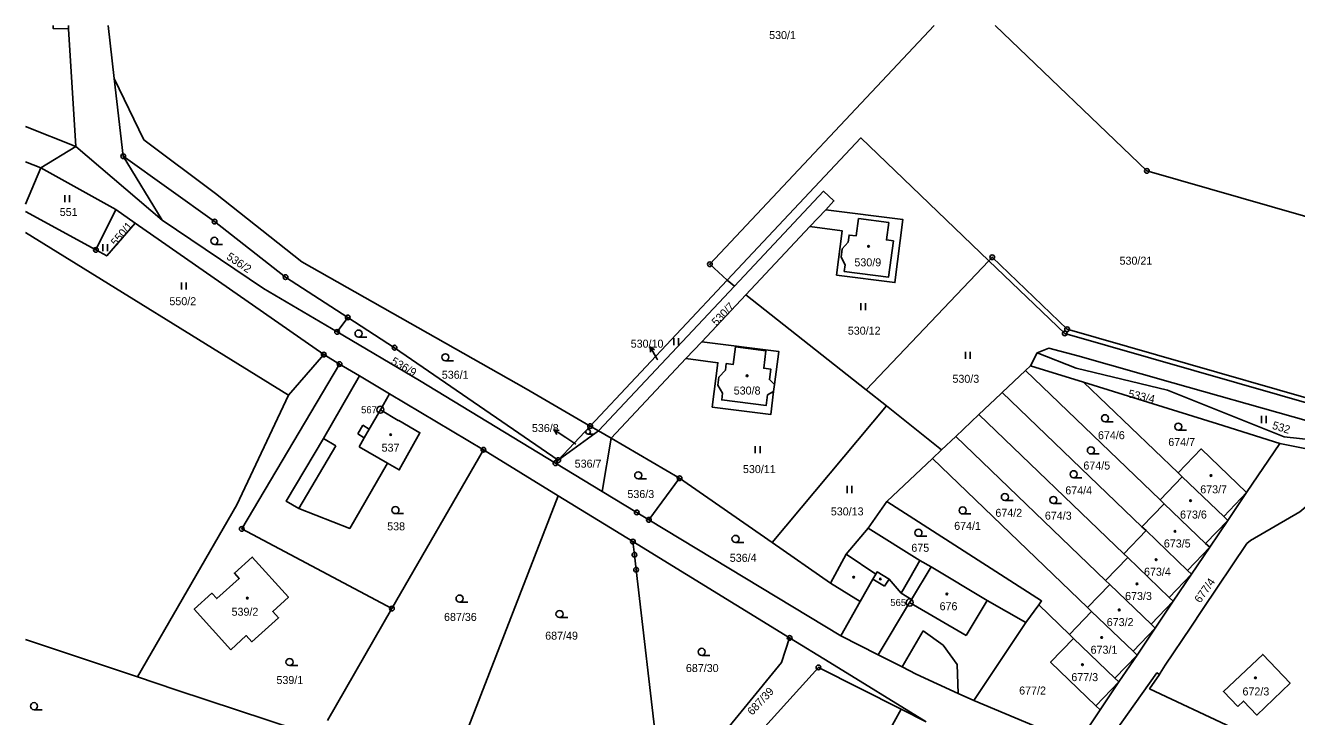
# Model space of a CAD drawing. Extents: x -749778 to -749372, y -967291 to -966955.
# Drawn here: x -749777.6 to -749507.7, y -967101.9 to -966955.1 of the extents above; entities that cross this region are included whole.
import ezdxf

# ---------------------------------------------------------------- set-up
doc = ezdxf.new("R2010")
doc.units = 0
for name, color, linetype in [('Hranice parcel', 7, 'Continuous'), ('Parcelní čísla', 7, 'Continuous'), ('Pop  PČ popisy', 7, 'Continuous'), ('Vnitřní kresba', 7, 'Continuous'), ('Značky bodu BP', 7, 'Continuous'), ('Značky budov', 7, 'Continuous'), ('Značky kultur', 7, 'Continuous')]:
    doc.layers.add(name, color=color, linetype=linetype)

msp = doc.modelspace()

# ---------------------------------------------------------------- linework, layer by layer
at = {"layer": 'Hranice parcel'}
for p, q in [((-749768.49, -966955.06), (-749768.51, -966955.82)), ((-749768.51, -966955.82), (-749766.93, -966980.78)), ((-749756.87, -966982.87), (-749758.78, -966966.32)), ((-749766.93, -966980.78), (-749777.63, -966976.54)), ((-749774.34, -966985.3), (-749766.93, -966980.78)), ((-749766.93, -966980.78), (-749748.6, -966996.42)), ((-749748.6, -966996.42), (-749756.87, -966982.87)), ((-749774.34, -966985.3), (-749777.63, -966984.05)), ((-749758.43, -966994.19), (-749774.34, -966985.3)), ((-749758.43, -966994.19), (-749762.66, -967002.76)), ((-749754.33, -966997.05), (-749758.43, -966994.19)), ((-749611.05, -966997.82), (-749607.66, -966994.22)), ((-749714.28, -967025), (-749754.33, -966997.05)), ((-749721.74, -967033.62), (-749777.63, -966999.06)), ((-749624.66, -967012.31), (-749611.05, -966997.82)), ((-749573, -967005.05), (-749599.06, -967032.48)), ((-749657.69, -967040.19), (-749628.61, -967009.22)), ((-749627.02, -967010.45), (-749655.92, -967041.22)), ((-749627.02, -967010.45), (-749628.61, -967009.22)), ((-749634, -967022.26), (-749624.66, -967012.31)), ((-749599.06, -967032.48), (-749624.66, -967012.31)), ((-749711.43, -967020.19), (-749709.16, -967017.1)), ((-749637.38, -967025.86), (-749634, -967022.26)), ((-749721.74, -967033.62), (-749714.28, -967025)), ((-749714.28, -967025), (-749710.9, -967027.02)), ((-749706.67, -967029.54), (-749710.9, -967027.02)), ((-749653.26, -967042.77), (-749637.38, -967025.86)), ((-749564.16, -967027.37), (-749562.74, -967024.63)), ((-749700.29, -967033.34), (-749706.67, -967029.54)), ((-749570.18, -967033.07), (-749565.25, -967028.4)), ((-749565.25, -967028.4), (-749564.16, -967027.37)), ((-749536.64, -967055.87), (-749565.25, -967028.4)), ((-749564.16, -967027.37), (-749552.89, -967030.87)), ((-749532.8, -967050.13), (-749552.89, -967030.87)), ((-749680.37, -967045.22), (-749700.29, -967033.34)), ((-749599.06, -967032.48), (-749594.75, -967035.91)), ((-749540.5, -967061.59), (-749570.18, -967033.07)), ((-749619.07, -967064.92), (-749594.75, -967035.91)), ((-749594.75, -967035.91), (-749583.06, -967045.24)), ((-749580.06, -967042.41), (-749575.13, -967037.74)), ((-749544.33, -967067.31), (-749575.13, -967037.74)), ((-749664.47, -967047.42), (-749657.69, -967040.19)), ((-749655.92, -967041.22), (-749657.69, -967040.19)), ((-749655.92, -967041.22), (-749664.47, -967047.42)), ((-749655.92, -967041.22), (-749653.26, -967042.77)), ((-749653.26, -967042.77), (-749655.12, -967054.12)), ((-749638.69, -967051.26), (-749653.26, -967042.77)), ((-749583.06, -967045.24), (-749580.06, -967042.41)), ((-749548.22, -967073.01), (-749580.06, -967042.41)), ((-749699.81, -967078.98), (-749680.37, -967045.22)), ((-749680.37, -967045.22), (-749664.5, -967054.98)), ((-749583.06, -967045.24), (-749585.01, -967047.08)), ((-749518.29, -967054.31), (-749511.23, -967043.86)), ((-749664.47, -967047.42), (-749665.08, -967048.07)), ((-749655.12, -967054.12), (-749665.08, -967048.07)), ((-749585.01, -967047.08), (-749594.68, -967056.22)), ((-749552.05, -967078.75), (-749585.01, -967047.08)), ((-749645.2, -967060.11), (-749638.69, -967051.26)), ((-749619.07, -967064.92), (-749638.69, -967051.26)), ((-749531.93, -967050.96), (-749536.64, -967055.87)), ((-749532.8, -967050.13), (-749531.93, -967050.96)), ((-749684.12, -967105.59), (-749664.5, -967054.98)), ((-749664.5, -967054.98), (-749648.62, -967064.74)), ((-749535.77, -967056.7), (-749540.5, -967061.59)), ((-749536.64, -967055.87), (-749535.77, -967056.7)), ((-749522.26, -967060.23), (-749518.29, -967054.31)), ((-749604.44, -967084.74), (-749645.2, -967060.11)), ((-749540.5, -967061.59), (-749539.64, -967062.41)), ((-749526.12, -967065.95), (-749522.26, -967060.23)), ((-749648.62, -967064.74), (-749615.32, -967085.21)), ((-749539.64, -967062.41), (-749544.33, -967067.31)), ((-749606.68, -967073.54), (-749619.07, -967064.92)), ((-749603.32, -967067.37), (-749606.68, -967073.54)), ((-749544.33, -967067.31), (-749543.47, -967068.14)), ((-749529.98, -967071.67), (-749526.12, -967065.95)), ((-749543.47, -967068.14), (-749548.22, -967073.01)), ((-749533.84, -967077.4), (-749529.98, -967071.67)), ((-749547.35, -967073.84), (-749552.05, -967078.75)), ((-749548.22, -967073.01), (-749547.35, -967073.84)), ((-749565.15, -967081.89), (-749562.42, -967078.16)), ((-749562.42, -967078.16), (-749555.87, -967084.45)), ((-749537.69, -967083.12), (-749533.84, -967077.4)), ((-749699.81, -967078.98), (-749713.49, -967102.74)), ((-749551.19, -967079.58), (-749555.87, -967084.45)), ((-749552.05, -967078.75), (-749551.19, -967079.58)), ((-749576.24, -967098.5), (-749565.15, -967081.89)), ((-749541.54, -967088.85), (-749537.69, -967083.12)), ((-749555.87, -967084.45), (-749555.02, -967085.29)), ((-749545.4, -967094.56), (-749541.54, -967088.85)), ((-749549.38, -967100.48), (-749545.4, -967094.56)), ((-749576.24, -967098.5), (-749554.23, -967107.67)), ((-749586.36, -967103.02), (-749591.67, -967100.33))]:
    msp.add_line(p, q, dxfattribs=at)
for points in [[(-749768.51, -966955.82), (-749771.73, -966955.75), (-749771.71, -966955.06)], [(-749758.78, -966966.32), (-749760.08, -966955.06)], [(-749628.61, -967009.22), (-749632.26, -967005.8), (-749584.62, -966955.06)], [(-749571.65, -966955.06), (-749539.45, -966985.97), (-749459.63, -967008.89), (-749477.4, -967037.32)], [(-749758.78, -966966.32), (-749752.45, -966979.37), (-749737.29, -966990.76), (-749718.94, -967005.3), (-749671.29, -967032.27), (-749657.69, -967040.19)], [(-749573, -967005.05), (-749600.19, -966978.95), (-749628.61, -967009.22)], [(-749756.87, -966982.87), (-749737.45, -966996.74), (-749722.38, -967008.55), (-749709.16, -967017.1)], [(-749777.63, -966993.01), (-749774.34, -966985.3)], [(-749607.66, -966994.22), (-749605.92, -966992.36), (-749608.11, -966990.31), (-749627.02, -967010.45)], [(-749762.66, -967002.76), (-749777.63, -966994.6)], [(-749611.05, -966997.82), (-749604.17, -966998.69), (-749605.37, -967008.12), (-749592.97, -967009.7), (-749591.26, -966996.3), (-749607.66, -966994.22)], [(-749762.66, -967002.76), (-749760.36, -967004.02), (-749754.33, -966997.05)], [(-749711.43, -967020.19), (-749727.04, -967010.95), (-749748.6, -966996.42)], [(-749573, -967005.05), (-749572.31, -967004.33), (-749556.39, -967019.6), (-749480.03, -967041.53), (-749477.4, -967037.32)], [(-749474.68, -967044.11), (-749556.9, -967020.49), (-749573, -967005.05)], [(-749709.16, -967017.1), (-749699.22, -967023.53), (-749664.47, -967047.42)], [(-749665.08, -967048.07), (-749693.94, -967030.54), (-749711.43, -967020.19)], [(-749637.38, -967025.86), (-749630.55, -967026.73), (-749631.75, -967036.16), (-749619.35, -967037.74), (-749618.72, -967032.84), (-749618.54, -967031.36), (-749617.64, -967024.34), (-749634, -967022.26)], [(-749562.74, -967024.63), (-749560.29, -967023.62), (-749554.11, -967025.29), (-749533.97, -967031.01), (-749482.86, -967045.42)], [(-749710.9, -967027.02), (-749731.68, -967062.04), (-749699.81, -967078.98)], [(-749562.74, -967024.63), (-749554.44, -967027.88), (-749535.11, -967032.59), (-749510.28, -967042.45), (-749482.86, -967045.42)], [(-749706.67, -967029.54), (-749714.33, -967042.83), (-749722.22, -967056.16), (-749719.59, -967057.72), (-749708.76, -967061.94), (-749700.71, -967048.1), (-749698.23, -967049.52), (-749693.83, -967041.62), (-749698.3, -967038.99), (-749698.47, -967039.04), (-749702.24, -967036.72), (-749700.29, -967033.34)], [(-749552.89, -967030.87), (-749524.47, -967039.74), (-749511.23, -967043.86)], [(-749753.84, -967093.49), (-749732.73, -967056.95), (-749721.74, -967033.62)], [(-749575.13, -967037.74), (-749570.49, -967033.35), (-749570.18, -967033.07)], [(-749518.29, -967054.31), (-749527.96, -967045.04), (-749532.8, -967050.13)], [(-749511.23, -967043.86), (-749503.78, -967045.37), (-749490.3, -967048.1), (-749484.05, -967051.31)], [(-749522.26, -967060.23), (-749523.13, -967059.41), (-749531.93, -967050.96)], [(-749456.84, -967065.27), (-749475.82, -967057.43), (-749489.74, -967052.51), (-749500.28, -967053.21), (-749501.83, -967053.4), (-749502.46, -967054.34), (-749503.87, -967055.82), (-749506.95, -967058.39), (-749517.45, -967064.49), (-749518.23, -967065.16), (-749527.61, -967079.16), (-749530.11, -967082.89), (-749535.6, -967090.98), (-749536.66, -967092.72), (-749536.81, -967092.95)], [(-749645.2, -967060.11), (-749647.8, -967058.54), (-749655.12, -967054.12)], [(-749594.68, -967056.22), (-749598.63, -967061.85), (-749603.32, -967067.37)], [(-749594.68, -967056.22), (-749561.83, -967077.35), (-749562.42, -967078.16)], [(-749526.12, -967065.95), (-749526.97, -967065.13), (-749535.77, -967056.7)], [(-749648.62, -967064.74), (-749648.3, -967067.53), (-749647.94, -967070.71), (-749643.43, -967109.15)], [(-749529.98, -967071.67), (-749530.84, -967070.85), (-749539.64, -967062.41)], [(-749603.32, -967067.37), (-749597.01, -967071.63), (-749596.76, -967071.19), (-749594.16, -967072.69), (-749591.62, -967075.7), (-749589.79, -967072.47), (-749587.69, -967068.76), (-749585.3, -967070.11), (-749573.36, -967077.28), (-749565.15, -967081.89)], [(-749734.04, -967087.7), (-749741.77, -967079.12), (-749738.02, -967075.7), (-749737, -967076.84), (-749732.23, -967072.54), (-749733.26, -967071.41), (-749729.47, -967068.01), (-749721.76, -967076.51), (-749725.09, -967079.58), (-749723.88, -967080.9), (-749729.51, -967086), (-749730.74, -967084.72), (-749734.04, -967087.7)], [(-749533.84, -967077.4), (-749534.69, -967076.58), (-749543.47, -967068.14)], [(-749606.68, -967073.54), (-749600.38, -967077.49), (-749604.44, -967084.74)], [(-749537.69, -967083.12), (-749538.56, -967082.3), (-749547.35, -967073.84)], [(-749541.54, -967088.85), (-749542.39, -967088.02), (-749551.19, -967079.58)], [(-749777.63, -967085.52), (-749753.84, -967093.49)], [(-749632.88, -967109.8), (-749617.06, -967090.42), (-749615.32, -967085.21)], [(-749615.32, -967085.21), (-749606.8, -967090.45), (-749586.36, -967103.02)], [(-749604.44, -967084.74), (-749596.53, -967088.77), (-749591.42, -967091.37), (-749588.45, -967092.89), (-749579.53, -967096.99), (-749576.24, -967098.5)], [(-749549.38, -967100.48), (-749550.27, -967099.62), (-749559.92, -967090.32), (-749555.02, -967085.29)], [(-749555.02, -967085.29), (-749546.27, -967093.74), (-749545.4, -967094.56)], [(-749520.16, -967099.8), (-749523.2, -967096.56), (-749514.83, -967088.7), (-749509.04, -967094.79), (-749516.12, -967101.59), (-749518.91, -967098.62), (-749520.16, -967099.8)], [(-749624.65, -967108.54), (-749609.2, -967091.46), (-749591.67, -967100.33)], [(-749716.74, -967108.38), (-749719.68, -967104.83), (-749745.68, -967096.2), (-749753.84, -967093.49)], [(-749536.81, -967092.95), (-749537.33, -967092.65), (-749549.42, -967109.68)], [(-749536.81, -967092.95), (-749538.87, -967096), (-749521.44, -967104.24), (-749491.04, -967118.52)], [(-749591.67, -967100.33), (-749597.57, -967111.08), (-749601.91, -967114.2), (-749600.64, -967116.26), (-749606.62, -967124.91)], [(-749554.23, -967107.67), (-749553.8, -967107.04), (-749549.38, -967100.48)]]:
    msp.add_lwpolyline(points, dxfattribs=at)
at = {"layer": 'Pop  PČ popisy'}
for p, q in [((-749643.44, -967025.94), (-749644.94, -967023.34)), ((-749644.94, -967023.34), (-749644.01, -967023.96)), ((-749644.94, -967023.34), (-749644.87, -967024.46)), ((-749643.35, -967026.09), (-749643.44, -967025.94)), ((-749662.84, -967042.65), (-749665.36, -967041.02)), ((-749665.36, -967041.02), (-749664.24, -967041.14)), ((-749665.36, -967041.02), (-749664.79, -967041.98)), ((-749660.71, -967044.04), (-749662.84, -967042.65))]:
    msp.add_line(p, q, dxfattribs=at)
at = {"layer": 'Vnitřní kresba'}
for p, q in [((-749704.61, -967040.83), (-749702.24, -967036.72)), ((-749707.06, -967041.87), (-749706, -967040.03)), ((-749706, -967040.03), (-749704.61, -967040.83)), ((-749714.33, -967042.83), (-749711.7, -967044.39)), ((-749705.67, -967042.67), (-749707.06, -967041.87)), ((-749706.78, -967044.6), (-749705.67, -967042.67)), ((-749704.61, -967040.83), (-749705.67, -967042.67)), ((-749711.7, -967044.39), (-749719.59, -967057.72)), ((-749700.71, -967048.1), (-749706.78, -967044.6)), ((-749518.29, -967054.31), (-749523.13, -967059.41)), ((-749598.63, -967061.85), (-749587.69, -967068.76)), ((-749522.26, -967060.23), (-749526.97, -967065.13)), ((-749526.12, -967065.95), (-749530.84, -967070.85)), ((-749585.3, -967070.11), (-749589.45, -967077.04)), ((-749600.38, -967077.49), (-749597.64, -967072.72)), ((-749597.64, -967072.72), (-749597.01, -967071.63)), ((-749597.64, -967072.72), (-749595.16, -967074.22)), ((-749595.16, -967074.22), (-749594.16, -967072.69)), ((-749529.98, -967071.67), (-749534.69, -967076.58)), ((-749596.53, -967088.77), (-749589.84, -967077.68)), ((-749589.45, -967077.04), (-749591.62, -967075.7)), ((-749589.45, -967077.04), (-749589.84, -967077.68)), ((-749589.84, -967077.68), (-749577.8, -967084.66)), ((-749577.8, -967084.66), (-749573.36, -967077.28)), ((-749533.84, -967077.4), (-749538.56, -967082.3)), ((-749591.42, -967091.37), (-749586.97, -967083.68)), ((-749586.97, -967083.68), (-749582.71, -967086.75)), ((-749537.69, -967083.12), (-749542.39, -967088.02)), ((-749582.71, -967086.75), (-749579.76, -967090.87)), ((-749541.54, -967088.85), (-749546.27, -967093.74)), ((-749579.76, -967090.87), (-749579.53, -967096.99)), ((-749545.4, -967094.56), (-749550.27, -967099.62))]:
    msp.add_line(p, q, dxfattribs=at)
for points in [[(-749600.72, -966996.1), (-749594.29, -966996.94), (-749594.78, -967000.65), (-749593.29, -967000.84), (-749594.3, -967008.54), (-749603.72, -967007.34), (-749603.55, -967005.96), (-749604.36, -967004.27), (-749604.15, -967002.52), (-749602.91, -967001.13), (-749602.71, -966999.6), (-749601.22, -966999.79), (-749600.72, -966996.1)], [(-749626.82, -967023.37), (-749627.29, -967027.09), (-749628.78, -967026.9), (-749628.95, -967028.28), (-749630.36, -967029.77), (-749630.59, -967031.47), (-749629.6, -967033.23), (-749629.75, -967034.63), (-749620.32, -967035.84), (-749620.04, -967033.56), (-749618.72, -967032.84)], [(-749626.82, -967023.37), (-749620.37, -967024.18), (-749620.84, -967027.91), (-749619.35, -967028.09), (-749619.62, -967030.3), (-749618.54, -967031.36)]]:
    msp.add_lwpolyline(points, dxfattribs=at)
at = {"layer": 'Značky bodu BP'}
for centre, radius in [((-749756.87, -966982.87), 0.5), ((-749756.87, -966982.87), 0.0303), ((-749539.45, -966985.97), 0.5), ((-749539.45, -966985.97), 0.0303), ((-749737.45, -966996.74), 0.5), ((-749737.45, -966996.74), 0.0303), ((-749762.66, -967002.76), 0.5), ((-749762.66, -967002.76), 0.0303), ((-749632.26, -967005.8), 0.5), ((-749572.31, -967004.33), 0.5), ((-749572.31, -967004.33), 0.0303), ((-749722.38, -967008.55), 0.5), ((-749632.26, -967005.8), 0.0303), ((-749722.38, -967008.55), 0.0303), ((-749709.16, -967017.1), 0.5), ((-749709.16, -967017.1), 0.0303), ((-749711.43, -967020.19), 0.5), ((-749711.43, -967020.19), 0.0303), ((-749556.9, -967020.49), 0.5), ((-749556.9, -967020.49), 0.0303), ((-749556.39, -967019.6), 0.5), ((-749556.39, -967019.6), 0.0303), ((-749699.22, -967023.53), 0.5), ((-749699.22, -967023.53), 0.0303), ((-749714.28, -967025), 0.5), ((-749714.28, -967025), 0.0303), ((-749710.9, -967027.02), 0.5), ((-749710.9, -967027.02), 0.0303), ((-749702.24, -967036.72), 0.75), ((-749702.24, -967036.72), 0.03), ((-749657.69, -967040.19), 0.5), ((-749657.69, -967040.19), 0.0303), ((-749680.37, -967045.22), 0.5), ((-749680.37, -967045.22), 0.0303), ((-749665.08, -967048.07), 0.5), ((-749665.08, -967048.07), 0.0303), ((-749664.47, -967047.42), 0.5), ((-749664.47, -967047.42), 0.0303), ((-749638.69, -967051.26), 0.5), ((-749638.69, -967051.26), 0.0303), ((-749647.8, -967058.54), 0.5), ((-749647.8, -967058.54), 0.0303), ((-749731.68, -967062.04), 0.5), ((-749731.68, -967062.04), 0.0303), ((-749645.2, -967060.11), 0.5), ((-749645.2, -967060.11), 0.0303), ((-749648.62, -967064.74), 0.5), ((-749648.62, -967064.74), 0.0303), ((-749648.3, -967067.53), 0.5), ((-749648.3, -967067.53), 0.0303), ((-749647.94, -967070.71), 0.5), ((-749647.94, -967070.71), 0.0303), ((-749589.84, -967077.68), 0.75), ((-749589.84, -967077.68), 0.03), ((-749699.81, -967078.98), 0.5), ((-749699.81, -967078.98), 0.0303), ((-749615.32, -967085.21), 0.5), ((-749615.32, -967085.21), 0.0303), ((-749609.2, -967091.46), 0.5), ((-749609.2, -967091.46), 0.0303)]:
    msp.add_circle(centre, radius, dxfattribs=at)
at = {"layer": 'Značky budov'}
for centre in [(-749598.56, -967002.01), (-749624.36, -967029.5), (-749700.06, -967042), (-749525.83, -967050.7), (-749530.18, -967056.03), (-749533.49, -967062.55), (-749537.49, -967068.59), (-749601.74, -967072.29), (-749596.06, -967072.68), (-749541.55, -967073.72), (-749730.5, -967076.75), (-749581.93, -967075.87), (-749545.33, -967079.25), (-749549.07, -967085.11), (-749553.14, -967090.89), (-749516.39, -967093.68)]:
    msp.add_circle(centre, 0.175, dxfattribs=at)
at = {"layer": 'Značky kultur'}
for p, q in [((-749769.29, -966992.6), (-749769.29, -966991.1)), ((-749768.29, -966992.6), (-749768.29, -966991.1)), ((-749761.17, -967003.05), (-749761.17, -967001.55)), ((-749760.17, -967003.05), (-749760.17, -967001.55)), ((-749737.5, -967001.58), (-749735.75, -967001.58)), ((-749744.47, -967011.15), (-749744.47, -967009.65)), ((-749743.47, -967011.15), (-749743.47, -967009.65)), ((-749600.22, -967015.55), (-749600.22, -967014.05)), ((-749599.22, -967015.55), (-749599.22, -967014.05)), ((-749706.88, -967021.28), (-749705.13, -967021.28)), ((-749639.94, -967023.01), (-749639.94, -967021.51)), ((-749638.94, -967023.01), (-749638.94, -967021.51)), ((-749688.44, -967026.32), (-749686.69, -967026.32)), ((-749577.98, -967025.9), (-749577.98, -967024.4)), ((-749576.98, -967025.9), (-749576.98, -967024.4)), ((-749548.34, -967039.27), (-749546.59, -967039.27)), ((-749515.1, -967039.54), (-749515.1, -967038.04)), ((-749514.1, -967039.54), (-749514.1, -967038.04)), ((-749658.11, -967041.89), (-749656.94, -967041.89)), ((-749532.79, -967041.06), (-749531.04, -967041.06)), ((-749622.62, -967045.93), (-749622.62, -967044.43)), ((-749621.62, -967045.93), (-749621.62, -967044.43)), ((-749551.35, -967046.12), (-749549.6, -967046.12)), ((-749555.02, -967051.17), (-749553.27, -967051.17)), ((-749647.48, -967051.41), (-749645.73, -967051.41)), ((-749603.1, -967054.42), (-749603.1, -967052.92)), ((-749602.1, -967054.42), (-749602.1, -967052.92)), ((-749569.61, -967056.02), (-749567.86, -967056.02)), ((-749559.31, -967056.64), (-749557.56, -967056.64)), ((-749699.05, -967058.8), (-749697.3, -967058.8)), ((-749578.57, -967058.86), (-749576.82, -967058.86)), ((-749587.97, -967063.61), (-749586.22, -967063.61)), ((-749626.82, -967064.91), (-749625.07, -967064.91)), ((-749685.43, -967077.59), (-749683.68, -967077.59)), ((-749664.2, -967080.88), (-749662.45, -967080.88)), ((-749634, -967088.91), (-749632.25, -967088.91)), ((-749721.54, -967091.08), (-749719.79, -967091.08)), ((-749775.8, -967100.45), (-749774.05, -967100.45))]:
    msp.add_line(p, q, dxfattribs=at)
for centre, radius in [((-749737.5, -967000.83), 0.75), ((-749706.88, -967020.53), 0.75), ((-749688.44, -967025.57), 0.75), ((-749548.34, -967038.52), 0.75), ((-749532.79, -967040.31), 0.75), ((-749658.12, -967041.39), 0.502), ((-749551.35, -967045.37), 0.75), ((-749647.48, -967050.66), 0.75), ((-749555.02, -967050.42), 0.75), ((-749569.61, -967055.27), 0.75), ((-749559.31, -967055.89), 0.75), ((-749699.05, -967058.05), 0.75), ((-749578.57, -967058.11), 0.75), ((-749587.97, -967062.86), 0.75), ((-749626.82, -967064.16), 0.75), ((-749685.43, -967076.84), 0.75), ((-749664.2, -967080.13), 0.75), ((-749634, -967088.16), 0.75), ((-749721.54, -967090.33), 0.75), ((-749775.8, -967099.7), 0.75)]:
    msp.add_circle(centre, radius, dxfattribs=at)

# ---------------------------------------------------------------- texts
at = {"layer": 'Parcelní čísla'}
for s, p in [('530/1', (-749619.68, -966957.96)), ('551', (-749770.34, -966995.55)), ('530/9', (-749601.57, -967006.25)), ('530/21', (-749545.26, -967005.9)), ('550/2', (-749747.05, -967014.51)), ('530/12', (-749602.97, -967020.77)), ('530/10', (-749649.08, -967023.53)), ('536/1', (-749689.2, -967030.13)), ('530/3', (-749580.75, -967030.99)), ('530/8', (-749627.2, -967033.49)), ('536/8', (-749670.06, -967041.45)), ('674/6', (-749549.84, -967042.98)), ('674/7', (-749534.91, -967044.42)), ('537', (-749701.98, -967045.62)), ('536/7', (-749660.98, -967049.02)), ('530/11', (-749625.24, -967050.18)), ('674/5', (-749552.94, -967049.42)), ('536/3', (-749649.78, -967055.48)), ('674/4', (-749556.78, -967054.69)), ('673/7', (-749528.12, -967054.48)), ('530/13', (-749606.58, -967059.17)), ('674/2', (-749571.63, -967059.47)), ('674/3', (-749561.12, -967060.07)), ('673/6', (-749532.41, -967059.84)), ('538', (-749700.8, -967062.34)), ('674/1', (-749580.38, -967062.24)), ('673/5', (-749535.85, -967065.98)), ('536/4', (-749628.04, -967069.03)), ('675', (-749589.48, -967066.9)), ('673/4', (-749540.06, -967071.99)), ('673/3', (-749544.08, -967077.14)), ('676', (-749583.48, -967079.32)), ('539/2', (-749733.85, -967080.49)), ('687/36', (-749688.73, -967081.59)), ('673/2', (-749547.98, -967082.69)), ('687/49', (-749667.24, -967085.57)), ('673/1', (-749551.41, -967088.56)), ('687/30', (-749637.36, -967092.45)), ('539/1', (-749724.32, -967095)), ('677/3', (-749555.5, -967094.38)), ('677/2', (-749566.58, -967097.23)), ('672/3', (-749519.15, -967097.42))]:
    msp.add_text(s, height=1.7, dxfattribs=at).set_placement(p)
for s, rotation, p in [('550/1', 50, (-749758.37, -967002.08)), ('536/2', 326, (-749735.08, -967004.58)), ('530/7', 46, (-749630.86, -967019.02)), ('536/9', 330, (-749700.13, -967026.89)), ('533/4', 347, (-749543.53, -967034.06)), ('532', 343, (-749512.97, -967040.74)), ('677/4', 55, (-749528.12, -967077.92)), ('687/39', 47, (-749623.27, -967101.76))]:
    msp.add_text(s, height=1.7, rotation=rotation, dxfattribs=at).set_placement(p)
at = {"layer": 'Značky bodu BP'}
for s, p in [('567', (-749706.34, -967037.47)), ('565', (-749593.94, -967078.43))]:
    msp.add_text(s, height=1.5, dxfattribs=at).set_placement(p)

doc.saveas('drawing.dxf')
